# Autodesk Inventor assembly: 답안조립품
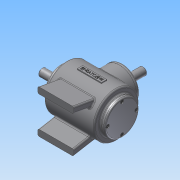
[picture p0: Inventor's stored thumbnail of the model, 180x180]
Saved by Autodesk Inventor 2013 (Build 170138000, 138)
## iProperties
Created: 2015-01
Part Number: 답안조립품
Document SubType Name: Assembly
Designer: Administrator
Author: Administrator
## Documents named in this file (15)
- C:\Users\Administrator\Desktop\450106V1017\답안조립품.iam
- C:\Users\Administrator\Desktop\450106V1017\본체.ipt
- C:\Users\Administrator\Desktop\450106V1017\M4.ipt
- C:\Users\Administrator\Desktop\450106V1017\메인 베벨기어.ipt
- C:\Users\Administrator\Desktop\450106V1017\메인 축.ipt
- 메인 축.ipt
- C:\Users\Administrator\Desktop\450106V1017\베어링 6203.ipt
- C:\Users\Administrator\Desktop\450106V1017\서브 베벨기어.ipt
- C:\Users\Administrator\Desktop\450106V1017\서브 축.ipt
- 서브 축.ipt
- C:\Users\Administrator\Desktop\450106V1017\오일실.ipt
- C:\Users\Administrator\Desktop\450106V1017\커버.ipt
- C:\Users\Administrator\Desktop\450106V1017\커버2.ipt
- C:\Users\Administrator\Desktop\450106V1017\키 4x4.ipt
- C:\Users\Administrator\Desktop\450106V1017\키 5x5.ipt
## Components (12 placed, 1 different names)
1. M4:3
2. M4:4
3. M4:5
4. M4:6
5. M4:1
6. M4:7
7. M4:8
8. M4:9
9. M4:2
10. M4:10
11. M4:11
12. M4:12
